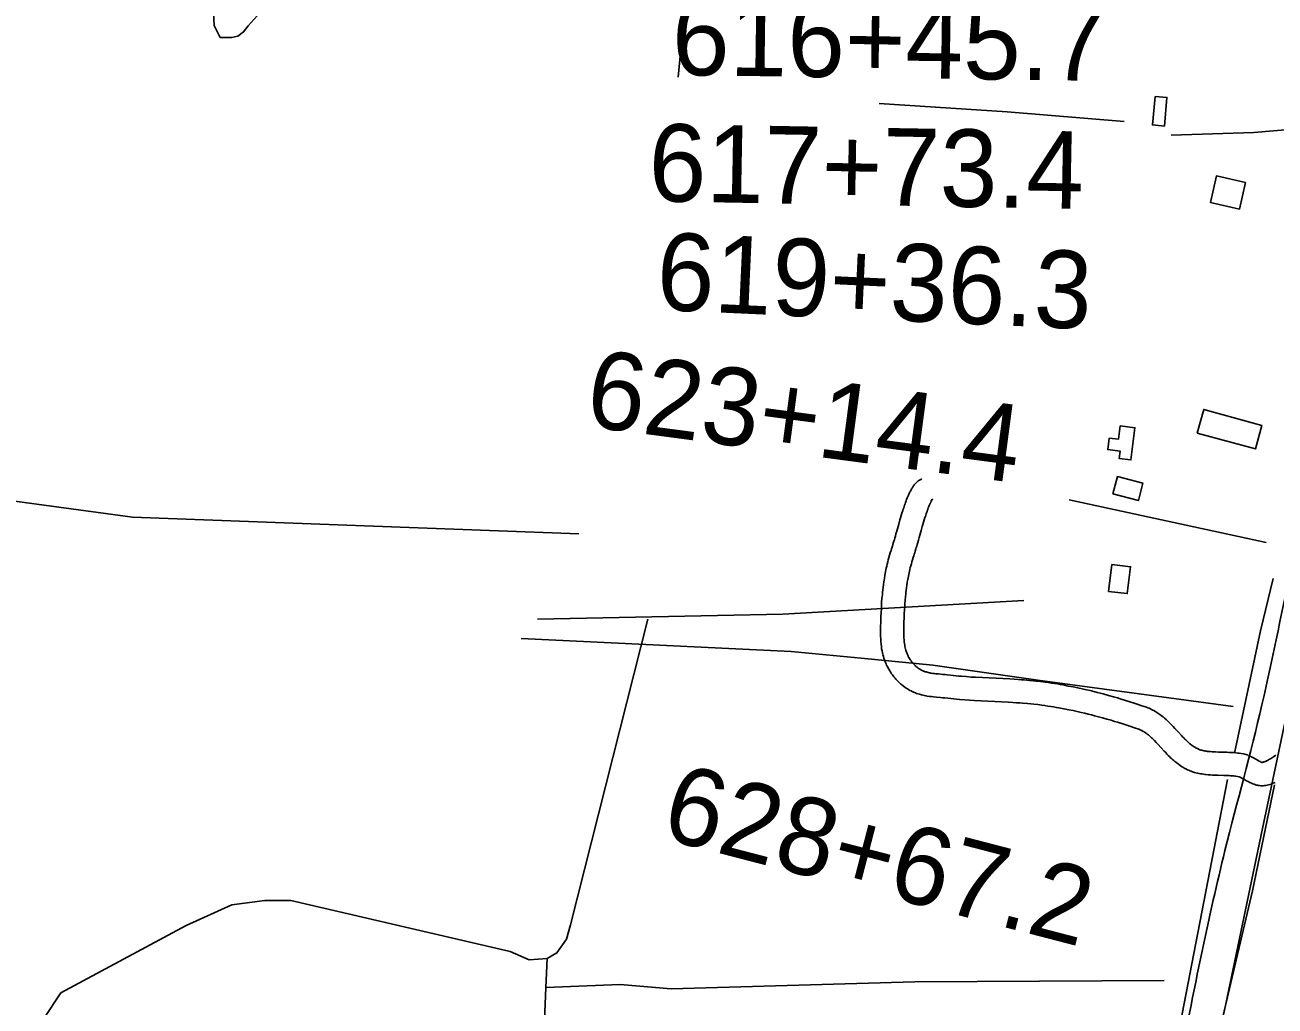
# Model space of a CAD drawing. Extents: x 3161564 to 3199464, y 849354 to 874788.
# Drawn here: x 3173493 to 3175105, y 867288 to 868553 of the extents above; entities that cross this region are included whole.
import ezdxf

# ---------------------------------------------------------------- set-up
doc = ezdxf.new("R2010")
doc.units = 0
for name, color, linetype in [('V-BLDG-OTLN', 7, 'Continuous'), ('V-LEVE-TOET', 7, 'Continuous'), ('V-ROAD-CNTR', 7, 'Continuous'), ('V-SITE-VEGE', 7, 'Continuous'), ('V-SURV-IDEN', 7, 'Continuous'), ('V-TOPO-SHOR', 7, 'Continuous')]:
    doc.layers.add(name, color=color, linetype=linetype)

msp = doc.modelspace()

# ---------------------------------------------------------------- linework, layer by layer
at = {"layer": 'V-BLDG-OTLN'}
for points in [[(3174950, 868461.2), (3174965.4, 868459.8), (3174962, 868423), (3174946.6, 868424.4)], [(3175021.4, 868324.4), (3175029.2, 868358.6), (3175066.5, 868350.1), (3175058.7, 868315.9)], [(3175004.4, 868026.9), (3175012.7, 868057.4), (3175087.9, 868036.7), (3175079.6, 868006.3)], [(3174904.9, 868036), (3174924, 868033.6), (3174918.8, 867992.3), (3174903.6, 867994.2), (3174904.8, 868003.5), (3174889.1, 868005.5), (3174891, 868020.4), (3174902.7, 868018.9)], [(3174895.5, 867948.4), (3174901.4, 867970.8), (3174934.4, 867962.2), (3174928.6, 867939.7)], [(3174890.1, 867822.6), (3174894.3, 867857.2), (3174918.4, 867854.3), (3174914.2, 867819.7)]]:
    msp.add_lwpolyline(points, close=True, dxfattribs=at)
at = {"layer": 'V-LEVE-TOET'}
msp.add_lwpolyline([(3175154.6, 867830.1), (3175088.5, 867516.8), (3175040.9, 867288.4), (3174990, 867058.9), (3174936.5, 866816.4), (3174866.7, 866497.8), (3174796, 866129.7), (3174741.4, 865818.9), (3174730.7, 865717), (3174727.2, 865653.8), (3174728.9, 865616)], dxfattribs=at)
at = {"layer": 'V-ROAD-CNTR'}
for points in [[(3174649.2, 867967.6), (3174648, 867967), (3174646.3, 867966.1), (3174644.7, 867965.1), (3174643.4, 867964), (3174642.3, 867963), (3174641.2, 867961.9), (3174640.3, 867960.9), (3174639.4, 867959.9), (3174638.6, 867958.8), (3174637.9, 867957.8), (3174637.2, 867956.8), (3174636.6, 867955.8), (3174636, 867954.8), (3174635.4, 867953.8), (3174634.9, 867952.8), (3174634.4, 867951.9), (3174633.8, 867950.9), (3174633.4, 867949.9), (3174632.9, 867948.9), (3174632.5, 867947.9), (3174632, 867946.9), (3174631.2, 867945), (3174630.4, 867943.1), (3174629.6, 867941.2), (3174628.9, 867939.3), (3174628.2, 867937.4), (3174627.6, 867935.6), (3174626.9, 867933.8), (3174626.3, 867932), (3174625.8, 867930.2), (3174625.2, 867928.5), (3174624.7, 867926.8), (3174623.6, 867923.6), (3174622.7, 867920.5), (3174621.8, 867917.5), (3174621, 867914.7), (3174619.5, 867909.5), (3174616.9, 867900.3), (3174615.9, 867896.9), (3174615.1, 867894), (3174614.4, 867891.5), (3174613.8, 867889.3), (3174613.2, 867887.5), (3174612.7, 867885.9), (3174611.9, 867883.1), (3174611.3, 867881.1), (3174610.9, 867879.6), (3174610.2, 867877.5), (3174609.5, 867875.3), (3174608.5, 867872.3), (3174607.6, 867869.2), (3174606.8, 867866.2), (3174606, 867863.3), (3174605.3, 867860.5), (3174604.6, 867857.9), (3174604, 867855.2), (3174603.4, 867852.7), (3174602.9, 867850.3), (3174602.4, 867847.9), (3174601.6, 867843.4), (3174600.9, 867839.1), (3174600.2, 867835.1), (3174599.7, 867831.3), (3174599.3, 867827.8), (3174598.9, 867824.6), (3174598.5, 867821.5), (3174598.3, 867818.6), (3174597.8, 867813.3), (3174597.4, 867808.6), (3174597.2, 867804.6), (3174597, 867801), (3174596.7, 867794.9), (3174596.5, 867790.2), (3174596.2, 867783.3), (3174596.1, 867776.5), (3174596, 867772.4), (3174596, 867768.5), (3174596, 867764.8), (3174596.2, 867761.2), (3174596.4, 867757.8), (3174596.7, 867754.6), (3174597, 867751.5), (3174597.4, 867748.6), (3174597.9, 867745.9), (3174598.5, 867743.3), (3174599, 867741.1)], [(3174661.2, 867940), (3174661.3, 867940.1), (3174662, 867940.5), (3174662.4, 867940.8), (3174662.7, 867941), (3174662.9, 867941.2), (3174663, 867941.3), (3174663, 867941.2), (3174662.9, 867941.1), (3174662.7, 867940.9), (3174662.5, 867940.7), (3174662.3, 867940.4), (3174662.1, 867940), (3174661.8, 867939.6), (3174661.6, 867939.1), (3174661.3, 867938.6), (3174661, 867938), (3174660.7, 867937.4), (3174660.4, 867936.8), (3174660.1, 867936.2), (3174659.8, 867935.5), (3174659.5, 867934.9), (3174658.8, 867933.4), (3174658.2, 867931.9), (3174657.6, 867930.4), (3174657, 867928.8), (3174656.4, 867927.2), (3174655.9, 867925.6), (3174655.3, 867924), (3174654.8, 867922.5), (3174654.3, 867920.9), (3174653.8, 867919.3), (3174653.3, 867917.8), (3174652.3, 867914.7), (3174651.4, 867911.8), (3174650.6, 867909), (3174649.8, 867906.3), (3174648.3, 867901.2), (3174645.8, 867892.1), (3174644.8, 867888.7), (3174644, 867885.8), (3174643.2, 867883.2), (3174642.6, 867881), (3174642, 867879), (3174641.5, 867877.4), (3174640.7, 867874.5), (3174640, 867872.3), (3174639.5, 867870.7), (3174638.8, 867868.4), (3174638.1, 867866.2), (3174637.2, 867863.4), (3174636.4, 867860.7), (3174635.7, 867858.1), (3174635, 867855.7), (3174634.3, 867853.2), (3174633.8, 867850.9), (3174633.2, 867848.6), (3174632.7, 867846.4), (3174632.3, 867844.2), (3174631.9, 867842.2), (3174631.1, 867838.1), (3174630.5, 867834.3), (3174629.9, 867830.7), (3174629.4, 867827.3), (3174629, 867824.2), (3174628.7, 867821.2), (3174628.4, 867818.4), (3174628.1, 867815.8), (3174627.7, 867810.8), (3174627.4, 867806.5), (3174627.1, 867802.7), (3174626.9, 867799.4), (3174626.6, 867793.5), (3174626.4, 867789.1), (3174626.2, 867782.5), (3174626.1, 867775.8), (3174626, 867772.1), (3174626, 867768.7), (3174626, 867765.5), (3174626.1, 867762.7), (3174626.3, 867760), (3174626.5, 867757.6), (3174626.8, 867755.4), (3174627.1, 867753.4), (3174627.4, 867751.5), (3174627.7, 867749.8), (3174628.2, 867748)], [(3174628.1, 867748.5), (3174628.5, 867746.8), (3174628.9, 867745.5), (3174629.3, 867744.2), (3174629.7, 867743.1), (3174630.2, 867742.1), (3174630.6, 867741.1), (3174631, 867740.2), (3174631.4, 867739.3), (3174631.8, 867738.5), (3174632.2, 867737.8), (3174632.6, 867737.1), (3174633.4, 867735.8), (3174634.1, 867734.6), (3174634.8, 867733.7), (3174635.4, 867732.8), (3174636, 867732.1), (3174636.4, 867731.4), (3174637.4, 867730.2), (3174638.2, 867729.4), (3174638.8, 867728.8), (3174639.7, 867727.8), (3174640.7, 867726.8), (3174641.2, 867726.3), (3174641.8, 867725.8), (3174642.3, 867725.4), (3174642.7, 867725), (3174643.8, 867724.2), (3174644.7, 867723.5), (3174645.6, 867722.8), (3174646.5, 867722.3), (3174647.3, 867721.7), (3174648.1, 867721.3), (3174648.9, 867720.9), (3174649.7, 867720.5), (3174650.5, 867720.1), (3174651.2, 867719.8), (3174652, 867719.5), (3174652.7, 867719.3), (3174653.3, 867719), (3174654.8, 867718.6), (3174656.2, 867718.2), (3174657.5, 867717.9), (3174658.7, 867717.6), (3174659.9, 867717.4), (3174661, 867717.2), (3174663.4, 867716.8), (3174665.5, 867716.5), (3174667.3, 867716.3), (3174670.8, 867716), (3174676.3, 867715.5), (3174679.2, 867715.2), (3174682.1, 867714.9), (3174686, 867714.4), (3174689.7, 867714), (3174693.3, 867713.7), (3174696.7, 867713.3), (3174700.1, 867713.1), (3174706.6, 867712.6), (3174712.8, 867712.1), (3174718.6, 867711.8), (3174762.8, 867709.6), (3174768.4, 867709.3), (3174773.3, 867708.9), (3174777.6, 867708.6), (3174781.4, 867708.3), (3174788.1, 867707.8), (3174793, 867707.3), (3174796.8, 867706.9), (3174802.4, 867706.2), (3174808.1, 867705.5), (3174812.3, 867704.9), (3174816.3, 867704.3), (3174820.3, 867703.7), (3174824.1, 867703.1), (3174827.7, 867702.4), (3174831.3, 867701.8), (3174838.1, 867700.5), (3174844.6, 867699.3), (3174850.6, 867698), (3174856.2, 867696.8), (3174861.5, 867695.6), (3174866.4, 867694.5), (3174871, 867693.4), (3174875.3, 867692.3), (3174879.3, 867691.3), (3174883, 867690.3)], [(3174599.1, 867740.6), (3174599.7, 867738.5), (3174600.3, 867736.4), (3174601, 867734.4), (3174601.7, 867732.5), (3174602.4, 867730.7), (3174603.1, 867729), (3174603.8, 867727.5), (3174604.5, 867726), (3174605.2, 867724.6), (3174605.9, 867723.4), (3174606.6, 867722.1), (3174607.9, 867720), (3174609.1, 867718.1), (3174610.2, 867716.4), (3174611.3, 867714.9), (3174612.2, 867713.7), (3174613.1, 867712.5), (3174614.7, 867710.7), (3174615.9, 867709.3), (3174616.9, 867708.2), (3174618.3, 867706.7), (3174619.9, 867705.2), (3174620.8, 867704.3), (3174621.7, 867703.5), (3174622.7, 867702.7), (3174623.6, 867701.8), (3174625.4, 867700.4), (3174627.2, 867699.1), (3174628.9, 867697.9), (3174630.6, 867696.8), (3174632.2, 867695.8), (3174633.9, 867694.9), (3174635.4, 867694.1), (3174636.9, 867693.3), (3174638.4, 867692.7), (3174639.8, 867692.1), (3174641.2, 867691.5), (3174642.5, 867691), (3174643.9, 867690.6), (3174646.3, 867689.8), (3174648.6, 867689.2), (3174650.7, 867688.6), (3174652.6, 867688.2), (3174654.5, 867687.9), (3174656.2, 867687.6), (3174659.2, 867687.1), (3174661.9, 867686.8), (3174664.2, 867686.5), (3174668, 867686.1), (3174673.5, 867685.6), (3174676.1, 867685.4), (3174678.7, 867685.1), (3174682.7, 867684.6), (3174686.6, 867684.2), (3174690.4, 867683.8), (3174694.1, 867683.5), (3174697.6, 867683.2), (3174704.5, 867682.6), (3174710.9, 867682.2), (3174716.9, 867681.8), (3174761.1, 867679.6), (3174766.6, 867679.3), (3174771.3, 867679), (3174775.4, 867678.7), (3174779, 867678.4), (3174785.3, 867677.9), (3174790, 867677.4), (3174793.5, 867677.1), (3174798.8, 867676.5), (3174804, 867675.8), (3174808, 867675.2), (3174811.8, 867674.6), (3174815.5, 867674), (3174819.1, 867673.5), (3174822.6, 867672.9), (3174826, 867672.3), (3174832.5, 867671.1), (3174838.6, 867669.9), (3174844.4, 867668.7), (3174849.7, 867667.5), (3174854.7, 867666.4), (3174859.4, 867665.3), (3174863.8, 867664.2), (3174867.9, 867663.2), (3174871.8, 867662.2), (3174875.4, 867661.3)], [(3174883.2, 867690.3), (3174890.1, 867688.4), (3174896.3, 867686.6), (3174901.7, 867685.1), (3174906.4, 867683.7), (3174910.5, 867682.4), (3174917.6, 867680.2), (3174923, 867678.4), (3174927, 867677.1), (3174933, 867675.1), (3174939.1, 867673), (3174940.7, 867672.4), (3174942.4, 867671.7), (3174944, 867671), (3174945.6, 867670.3), (3174947.1, 867669.5), (3174948.5, 867668.7), (3174949.9, 867667.9), (3174951.2, 867667.2), (3174952.5, 867666.3), (3174953.8, 867665.5), (3174955, 867664.7), (3174956.2, 867663.9), (3174958.3, 867662.2), (3174960.4, 867660.6), (3174962.3, 867658.9), (3174964.2, 867657.3), (3174965.9, 867655.7), (3174967.5, 867654.2), (3174969, 867652.7), (3174970.5, 867651.2), (3174973.2, 867648.4), (3174975.7, 867645.8), (3174980.1, 867640.9), (3174983.9, 867636.8), (3174985.5, 867635.1), (3174987, 867633.6), (3174988.4, 867632.1), (3174989.6, 867630.9), (3174990.8, 867629.7), (3174991.9, 867628.7), (3174993, 867627.7), (3174993.9, 867626.9), (3174994.8, 867626.1), (3174995.7, 867625.4), (3174996.4, 867624.8), (3174997.9, 867623.7), (3174999.2, 867622.8), (3175000.3, 867622), (3175001.2, 867621.4), (3175002.1, 867621), (3175002.8, 867620.5), (3175003.4, 867620.2), (3175004.6, 867619.7), (3175005.4, 867619.3), (3175006, 867619), (3175006.9, 867618.7), (3175007.9, 867618.3), (3175009.2, 867617.9), (3175010.4, 867617.6), (3175011.7, 867617.3), (3175012.9, 867617), (3175014.1, 867616.8), (3175015.4, 867616.6), (3175016.6, 867616.4), (3175017.8, 867616.2), (3175018.9, 867616.1), (3175021.3, 867615.8), (3175023.6, 867615.7), (3175025.8, 867615.5), (3175027.9, 867615.4), (3175032, 867615.3), (3175039.5, 867615.1), (3175042.4, 867615), (3175045, 867614.9), (3175047.3, 867614.8), (3175049.3, 867614.7), (3175051.1, 867614.6), (3175054.2, 867614.3), (3175056.6, 867614), (3175058.5, 867613.8), (3175061.2, 867613.4), (3175064.1, 867612.8), (3175065.7, 867612.5), (3175067.2, 867612), (3175068.7, 867611.6), (3175069.8, 867611.1)], [(3174875.3, 867661.3), (3174882.1, 867659.4), (3174888, 867657.8), (3174893.2, 867656.3), (3174897.7, 867654.9), (3174901.6, 867653.7), (3174908.5, 867651.6), (3174913.7, 867649.9), (3174917.5, 867648.6), (3174923.3, 867646.7), (3174929, 867644.7), (3174929.9, 867644.4), (3174930.8, 867644), (3174931.6, 867643.7), (3174932.4, 867643.3), (3174933.2, 867642.9), (3174934, 867642.4), (3174934.8, 867642), (3174935.6, 867641.6), (3174936.3, 867641.1), (3174937.1, 867640.6), (3174937.8, 867640.1), (3174938.5, 867639.6), (3174940, 867638.5), (3174941.4, 867637.4), (3174942.8, 867636.2), (3174944.1, 867635), (3174945.4, 867633.8), (3174946.7, 867632.6), (3174947.9, 867631.4), (3174949.1, 867630.2), (3174951.5, 867627.8), (3174953.7, 867625.4), (3174958, 867620.6), (3174961.9, 867616.4), (3174963.7, 867614.5), (3174965.4, 867612.7), (3174967, 867611), (3174968.6, 867609.5), (3174970.1, 867608), (3174971.6, 867606.7), (3174972.9, 867605.4), (3174974.3, 867604.2), (3174975.5, 867603.1), (3174976.7, 867602.1), (3174978, 867601.2), (3174980.1, 867599.5), (3174982.2, 867598.1), (3174984, 867596.8), (3174985.7, 867595.8), (3174987.2, 867594.9), (3174988.5, 867594.2), (3174989.7, 867593.5), (3174991.8, 867592.5), (3174993.4, 867591.8), (3174994.7, 867591.2), (3174996.6, 867590.5), (3174998.5, 867589.8), (3175000.7, 867589.1), (3175002.8, 867588.6), (3175004.9, 867588.1), (3175006.8, 867587.6), (3175008.7, 867587.3), (3175010.5, 867587), (3175012.3, 867586.7), (3175014, 867586.5), (3175015.6, 867586.3), (3175018.7, 867585.9), (3175021.6, 867585.7), (3175024.2, 867585.6), (3175026.7, 867585.5), (3175031.1, 867585.3), (3175038.7, 867585.1), (3175041.4, 867585), (3175043.7, 867585), (3175045.7, 867584.9), (3175047.3, 867584.8), (3175048.7, 867584.7), (3175051.3, 867584.5), (3175053, 867584.3), (3175054.3, 867584.1), (3175056.2, 867583.8), (3175057.9, 867583.5), (3175058.2, 867583.4), (3175058.4, 867583.3), (3175058.7, 867583.2), (3175059.3, 867583)], [(3175070.2, 867611), (3175071.2, 867610.6), (3175072.4, 867610), (3175074.4, 867609.1), (3175076.2, 867608.2), (3175077.8, 867607.3), (3175082.8, 867604.4), (3175084.4, 867603.5), (3175085.6, 867602.9), (3175086.5, 867602.4), (3175087.2, 867602.2), (3175087.7, 867602), (3175088, 867601.9), (3175088.2, 867601.8), (3175088.3, 867601.8), (3175088.3, 867601.8), (3175088.1, 867601.8), (3175088.2, 867601.8), (3175088.1, 867601.8), (3175087.8, 867601.8), (3175087.7, 867601.8), (3175087.5, 867601.8), (3175088.1, 867601.9), (3175088.8, 867602.1), (3175089.6, 867602.3), (3175090.3, 867602.5), (3175091, 867602.8), (3175091.7, 867603), (3175092.4, 867603.3), (3175093.1, 867603.6), (3175093.7, 867603.9), (3175095.1, 867604.6), (3175096.4, 867605.2), (3175097.7, 867605.9), (3175098.8, 867606.6), (3175100, 867607.3), (3175101, 867608), (3175102, 867608.6), (3175103.9, 867610), (3175105.6, 867611.2)], [(3175058.9, 867583.2), (3175059.5, 867582.9), (3175059.9, 867582.8), (3175061, 867582.2), (3175062.1, 867581.7), (3175063.1, 867581.1), (3175068.1, 867578.2), (3175070.3, 867577.1), (3175072.3, 867576), (3175074.2, 867575.1), (3175076.1, 867574.3), (3175077.8, 867573.7), (3175079.4, 867573.1), (3175080.8, 867572.7), (3175082.2, 867572.4), (3175083.4, 867572.2), (3175084.7, 867572), (3175086.5, 867571.9), (3175088.1, 867571.8), (3175089.4, 867571.8), (3175091.2, 867572), (3175093, 867572.3), (3175094.8, 867572.7), (3175096.5, 867573.1), (3175098.1, 867573.5), (3175099.6, 867574), (3175101.1, 867574.5), (3175102.5, 867575), (3175103.8, 867575.5), (3175105.1, 867576.1)]]:
    msp.add_lwpolyline(points, dxfattribs=at)
msp.add_spline([(3176214.4, 872288), (3176116.8, 871676.9), (3176098.4, 871490.9), (3176090.7, 871415.9), (3176074.1, 871299.5), (3176058.2, 871187.5), (3176040.2, 871070.2), (3175999.5, 870899), (3175937.9, 870603.4), (3175884.9, 870365.8), (3175824.8, 870091.5), (3175790, 869942.8), (3175763.6, 869810), (3175731.1, 869705.4), (3175702.3, 869636.9), (3175675, 869598.5), (3175631, 869537.2), (3175579.4, 869482.4), (3175530.5, 869432.7), (3175484.1, 869377.7), (3175466.8, 869337.1), (3175448.9, 869288.9), (3175412.8, 869163.3), (3175354.2, 868894.7), (3175303.1, 868660), (3175288.3, 868569), (3175271.6, 868449), (3175249.1, 868331), (3175221.8, 868196), (3175175.8, 868026.9), (3175130.1, 867867), (3175087.9, 867676.4), (3175040.2, 867488.1), (3174985.4, 867232.3), (3174937.6, 866993.6), (3174859.7, 866658.8), (3174804.6, 866380.1), (3174764.5, 866230.5), (3174736.4, 866088.4)], degree=3, dxfattribs=at)
at = {"layer": 'V-SITE-VEGE'}
msp.add_lwpolyline([(3173792, 868565.2), (3173780.4, 868552.1), (3173774.6, 868544.5), (3173766.9, 868538.9), (3173759.3, 868537.1), (3173744.1, 868537.3), (3173736.7, 868552.6), (3173735.1, 868577.4)], dxfattribs=at)
at = {"layer": 'V-TOPO-SHOR'}
for p, q in [((3174345.4, 868596), (3174334.8, 868485.9)), ((3175093.3, 867885.5), (3174839.3, 867940.5)), ((3174780.7, 867810.9), (3174469.8, 867793.1)), ((3174469.8, 867793.1), (3174153.6, 867786.9)), ((3174480.5, 867745.1), (3174132.3, 867762)), ((3174974.3, 867222.9), (3175043.6, 867579.9))]:
    msp.add_line(p, q, dxfattribs=at)
for points in [[(3174910.3, 868429), (3174759.3, 868441.5), (3174594.1, 868452.1)], [(3174970.7, 868411.3), (3175077.3, 868414.8), (3175143, 868420.2), (3175164.4, 868436.1)], [(3174206.9, 867897), (3173631.3, 867918.3), (3172871.1, 868021.4)], [(3175052.4, 867613.7), (3175086.2, 867771.8), (3175102.2, 867839.3)], [(3174295.7, 867786.9), (3174196.2, 867392.5), (3174190.9, 867373.9), (3174178.5, 867356.1), (3174166, 867349), (3174142.9, 867347.2), (3174118.1, 867357.9), (3173835.6, 867423.6), (3173801.9, 867423.6), (3173759.2, 867418.3), (3173700.6, 867391.6), (3173539, 867304.6), (3173517.7, 867272.6), (3173507, 867222.9), (3173494.6, 867182)], [(3175050.7, 867674.1), (3174802, 867707.8), (3174663.4, 867727.4), (3174571, 867736.3), (3174480.5, 867745.1)], [(3175104, 867572.8), (3175075.5, 867436.1), (3174999.1, 867111), (3174899.7, 866654.5), (3174878.4, 866551.4), (3174794.9, 866187.3), (3174754, 865993.6), (3174736.2, 865942.1), (3174675.9, 865789.4), (3174553.3, 865494.5), (3174517.8, 865405.7), (3174508.9, 865363), (3174510.6, 865354.2), (3174688.3, 865352.4), (3174670.5, 865189), (3174466.2, 865192.5), (3174464.5, 865146.3)], [(3174166, 867349), (3174164.3, 867311.7), (3174260.2, 867315.3), (3174325.9, 867309.9), (3174640.3, 867318.8), (3174961.8, 867320.6)], [(3174164.3, 867311.7), (3174150, 866960), (3174141.2, 866784.1), (3174128.7, 866572.7), (3174116.3, 866386.2), (3174089.6, 865945.7), (3174611.9, 865977.7)]]:
    msp.add_lwpolyline(points, dxfattribs=at)

# ---------------------------------------------------------------- texts
at = {"layer": 'V-SURV-IDEN'}
for s, rotation, p in [('616+45.7', 359.2016, (3174326.4, 868488.9)), ('617+73.4', 358.9594, (3174296.2, 868326.1)), ('619+36.3', 357.4087, (3174305.6, 868186.1)), ('623+14.4', 352.4592, (3174213.2, 868036.1)), ('628+67.2', 345.4483, (3174310.1, 867505))]:
    msp.add_text(s, height=100, rotation=rotation, dxfattribs=at).set_placement(p)

doc.saveas('drawing.dxf')
